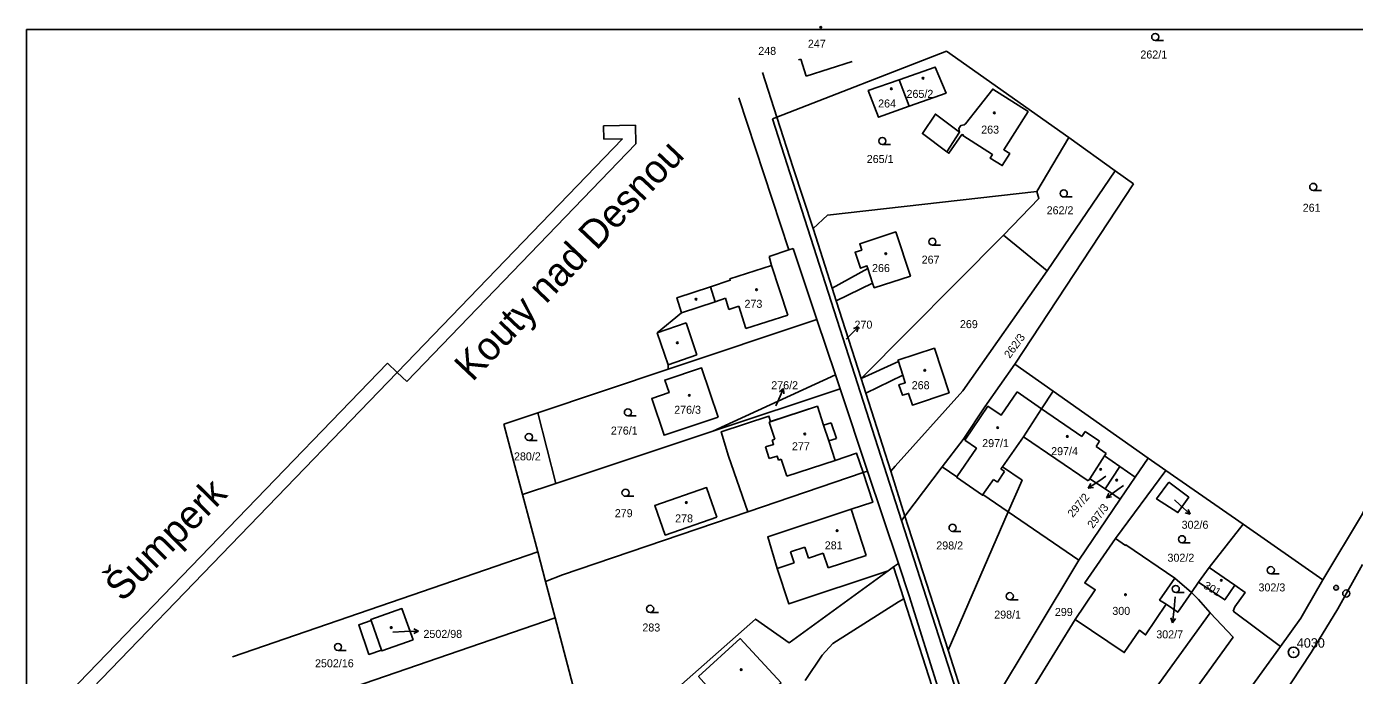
# Model space of a CAD drawing. Extents: x -558358 to -557517, y -1073785 to -1073189.
# Drawn here: x -558357.5 to -558075.5, y -1073327.3 to -1073189.5 of the extents above; entities that cross this region are included whole.
import ezdxf

# ---------------------------------------------------------------- set-up
doc = ezdxf.new("R2010")
doc.units = 0
for name, color, linetype in [('Hranice parcel', 7, 'Continuous'), ('Kolej', 7, 'Continuous'), ('Návěst místo trati', 7, 'Continuous'), ('Parcelní čísla', 7, 'Continuous'), ('Pop  PČ popisy', 7, 'Continuous'), ('Svazek obcí údolí Desné', 7, 'Continuous'), ('Vnitřní kresba', 7, 'Continuous'), ('Vrstva 1', 7, 'Continuous'), ('Vrstva 60', 7, 'Continuous'), ('Značky budov', 7, 'Continuous'), ('Značky kultur', 7, 'Continuous')]:
    doc.layers.add(name, color=color, linetype=linetype)

msp = doc.modelspace()

# ---------------------------------------------------------------- linework, layer by layer
at = {"layer": 'Hranice parcel'}
for p, q in [((-558198.15, -1073208.7), (-558162.11, -1073194.7)), ((-558162.11, -1073194.7), (-558136.18, -1073212.99)), ((-558198.15, -1073208.7), (-558201.24, -1073199.21)), ((-558170.04, -1073206.37), (-558172.21, -1073200.74)), ((-558195.64, -1073236.88), (-558206.21, -1073204.6)), ((-558199.08, -1073209.06), (-558198.15, -1073208.7)), ((-558171.71, -1073294.39), (-558199.08, -1073209.06)), ((-558136.18, -1073212.99), (-558142.95, -1073224.45)), ((-558136.18, -1073212.99), (-558126.3, -1073220.06)), ((-558140.75, -1073241.36), (-558126.3, -1073220.06)), ((-558126.3, -1073220.06), (-558122.4, -1073222.85)), ((-558122.4, -1073222.85), (-558147.61, -1073261.18)), ((-558190.48, -1073232.36), (-558186.42, -1073245.02)), ((-558180.27, -1073264.19), (-558150.02, -1073233.76)), ((-558150.02, -1073233.76), (-558140.75, -1073241.36)), ((-558199.8, -1073238.31), (-558195.64, -1073236.88)), ((-558194.69, -1073236.56), (-558195.64, -1073236.88)), ((-558194.69, -1073236.56), (-558189.64, -1073251.69)), ((-558186.42, -1073245.02), (-558185.55, -1073247.73)), ((-558185.55, -1073247.73), (-558180.27, -1073264.19)), ((-558221.22, -1073262.24), (-558189.64, -1073251.69)), ((-558189.64, -1073251.69), (-558185.73, -1073263.4)), ((-558248.97, -1073271.5), (-558221.22, -1073262.24)), ((-558211.74, -1073275.38), (-558185.73, -1073263.4)), ((-558185.73, -1073263.4), (-558184.74, -1073266.37)), ((-558147.61, -1073261.18), (-558139.47, -1073266.91)), ((-558180.27, -1073264.19), (-558179.28, -1073267.3)), ((-558184.74, -1073266.37), (-558211.74, -1073275.38)), ((-558184.74, -1073266.37), (-558178.92, -1073283.85)), ((-558179.28, -1073267.3), (-558173.98, -1073283.88)), ((-558139.47, -1073266.91), (-558119.31, -1073281.1)), ((-558256.16, -1073273.9), (-558248.97, -1073271.5)), ((-558248.97, -1073271.5), (-558245.1, -1073286.51)), ((-558254.1, -1073281.66), (-558256.16, -1073273.9)), ((-558185.53, -1073276.94), (-558186.65, -1073273.58)), ((-558211.74, -1073275.38), (-558245.1, -1073286.51)), ((-558252.2, -1073288.86), (-558254.1, -1073281.66)), ((-558170.97, -1073293.42), (-558163.02, -1073282.94)), ((-558128.43, -1073287.66), (-558125.31, -1073282.88)), ((-558122.04, -1073285.13), (-558125.31, -1073282.88)), ((-558122.04, -1073285.13), (-558119.31, -1073281.1)), ((-558119.31, -1073281.1), (-558115.55, -1073283.75)), ((-558204.33, -1073292.51), (-558179.86, -1073284.17)), ((-558179.86, -1073284.17), (-558178.92, -1073283.85)), ((-558178.92, -1073283.85), (-558172.36, -1073303.47)), ((-558173.98, -1073283.88), (-558170.97, -1073293.42)), ((-558126.22, -1073298.15), (-558115.55, -1073283.75)), ((-558125.21, -1073289.82), (-558122.04, -1073285.13)), ((-558115.55, -1073283.75), (-558099.14, -1073295.15)), ((-558245.1, -1073286.51), (-558252.2, -1073288.86)), ((-558128.43, -1073287.66), (-558125.21, -1073289.82)), ((-558252.2, -1073288.86), (-558248.97, -1073301.04)), ((-558134.04, -1073302.76), (-558125.21, -1073289.82)), ((-558171.71, -1073294.39), (-558170.97, -1073293.42)), ((-558161.8, -1073321.91), (-558170.97, -1073293.42)), ((-558149, -1073292.52), (-558161.8, -1073321.91)), ((-558149, -1073292.52), (-558134.04, -1073302.76)), ((-558106.35, -1073304.33), (-558099.14, -1073295.15)), ((-558099.14, -1073295.15), (-558082.18, -1073306.93)), ((-558313.8, -1073323.28), (-558248.97, -1073301.04)), ((-558248.97, -1073301.04), (-558247.31, -1073307.29)), ((-558156.12, -1073339.58), (-558134.04, -1073302.76)), ((-558174.53, -1073305.05), (-558173.36, -1073304.2)), ((-558173.36, -1073304.2), (-558172.36, -1073303.47)), ((-558171.18, -1073310.99), (-558173.36, -1073304.2)), ((-558106.35, -1073304.33), (-558108.61, -1073307.47)), ((-558100.91, -1073308.09), (-558106.35, -1073304.33)), ((-558247.31, -1073307.29), (-558245.27, -1073315.03)), ((-558113.61, -1073306.59), (-558110.09, -1073309.68)), ((-558110.09, -1073309.68), (-558108.61, -1073307.47)), ((-558171.18, -1073310.99), (-558158.75, -1073349.79)), ((-558146.53, -1073369.85), (-558106.1, -1073313.94)), ((-558101.25, -1073313.61), (-558091.21, -1073321.1)), ((-558245.27, -1073315.03), (-558311.02, -1073337.58)), ((-558245.27, -1073315.03), (-558240.15, -1073334.41)), ((-558153.86, -1073346.35), (-558134.81, -1073315.38)), ((-558156.12, -1073339.58), (-558161.8, -1073321.91))]:
    msp.add_line(p, q, dxfattribs=at)
for points in [[(-558172.21, -1073200.74), (-558164.51, -1073198.05), (-558162.21, -1073203.59), (-558170.04, -1073206.37)], [(-558172.21, -1073200.74), (-558178.74, -1073203.06), (-558176.58, -1073208.71), (-558170.04, -1073206.37)], [(-558159.35, -1073211.86), (-558164.49, -1073208.05), (-558167.25, -1073212.17), (-558162.05, -1073216.04), (-558161.61, -1073216.37), (-558158.87, -1073212.35), (-558158.54, -1073212.45), (-558158.65, -1073212.62), (-558152.39, -1073216.66), (-558152.86, -1073217.38), (-558150.28, -1073218.99), (-558148.7, -1073216.44), (-558149.97, -1073215.63), (-558144.81, -1073207.5), (-558152.32, -1073202.74), (-558158.11, -1073210.08), (-558158.35, -1073210.31), (-558159.12, -1073210.49), (-558159.48, -1073211.13), (-558159.35, -1073211.86)], [(-558198.15, -1073208.7), (-558194.7, -1073219.45), (-558190.48, -1073232.36)], [(-558190.48, -1073232.36), (-558187.44, -1073229.54), (-558142.95, -1073224.45)], [(-558142.95, -1073224.45), (-558142.49, -1073225.95), (-558150.02, -1073233.76)], [(-558185.55, -1073247.73), (-558177.82, -1073243.95), (-558177.49, -1073244.94), (-558169.79, -1073242.44), (-558172.9, -1073233.07), (-558180.56, -1073235.6), (-558180.13, -1073236.92), (-558181.54, -1073237.39), (-558180.43, -1073240.78), (-558179.03, -1073240.27), (-558178.83, -1073240.86), (-558186.42, -1073245.02)], [(-558199.8, -1073238.31), (-558199.29, -1073240.2), (-558208.14, -1073243.05), (-558208.05, -1073243.33), (-558212.29, -1073244.72), (-558219.4, -1073247.05), (-558218.39, -1073250.28), (-558223.57, -1073254.53), (-558221.27, -1073261.29), (-558221.22, -1073262.24)], [(-558140.75, -1073241.36), (-558158.68, -1073266.81), (-558173.01, -1073282.83), (-558173.98, -1073283.88)], [(-558179.28, -1073267.3), (-558171.41, -1073263.5), (-558170.89, -1073265.11), (-558172.23, -1073265.52), (-558171.5, -1073267.74), (-558170.17, -1073267.35), (-558169.36, -1073269.84), (-558161.57, -1073267.22), (-558164.69, -1073257.79), (-558172.45, -1073260.31), (-558172.35, -1073260.6), (-558180.27, -1073264.19)], [(-558210.64, -1073272.4), (-558222.13, -1073276.25), (-558224.75, -1073268.45), (-558221.07, -1073267.2), (-558221.97, -1073264.55), (-558214.15, -1073261.94), (-558210.64, -1073272.4)], [(-558163.02, -1073282.94), (-558158.61, -1073277.12), (-558153.96, -1073270.21), (-558147.61, -1073261.18)], [(-558149, -1073292.52), (-558146.08, -1073285.8), (-558150.24, -1073282.94), (-558145.79, -1073276.6), (-558141.97, -1073270.62), (-558139.47, -1073266.91)], [(-558186.65, -1073273.58), (-558188.24, -1073274.09), (-558189.55, -1073270.09), (-558199.49, -1073273.33), (-558199.86, -1073272.19), (-558209.99, -1073275.5), (-558208.43, -1073280.69), (-558204.33, -1073292.51)], [(-558179.86, -1073284.17), (-558181.24, -1073280.09), (-558185.8, -1073281.59), (-558187.15, -1073277.46), (-558185.53, -1073276.94)], [(-558163.02, -1073282.94), (-558159.92, -1073285.05), (-558159.98, -1073285.15), (-558154.48, -1073289), (-558154.38, -1073288.84), (-558149, -1073292.52)], [(-558125.31, -1073282.88), (-558128.57, -1073280.64), (-558131.66, -1073285.5), (-558128.43, -1073287.66)], [(-558179.86, -1073284.17), (-558177.8, -1073290.48), (-558182.36, -1073291.97), (-558200.11, -1073297.8), (-558198.12, -1073304.57), (-558195.6, -1073312.09), (-558174.53, -1073305.05)], [(-558210.92, -1073293.66), (-558221.88, -1073297.46), (-558224.1, -1073291.16), (-558213.08, -1073287.38), (-558210.92, -1073293.66)], [(-558114.88, -1073286.21), (-558110.67, -1073289.41), (-558112.99, -1073292.67), (-558117.52, -1073289.79), (-558114.88, -1073286.21)], [(-558247.31, -1073307.29), (-558243.66, -1073305.93), (-558204.33, -1073292.51)], [(-558140.29, -1073392.34), (-558154.66, -1073347.35), (-558171.71, -1073294.39)], [(-558134.81, -1073315.38), (-558130.55, -1073309.06), (-558132.76, -1073307.6), (-558126.22, -1073298.15)], [(-558113.61, -1073306.59), (-558124.02, -1073299.5), (-558124.12, -1073299.64), (-558126.22, -1073298.15)], [(-558237.16, -1073345.74), (-558202.67, -1073315.29), (-558195.58, -1073320.33), (-558174.53, -1073305.05)], [(-558172.36, -1073303.47), (-558170.06, -1073310.34), (-558157.85, -1073349.12), (-558143.83, -1073396.83)], [(-558115.48, -1073312.12), (-558116.87, -1073311.27), (-558113.61, -1073306.59)], [(-558108.61, -1073307.47), (-558103.03, -1073311.24), (-558100.91, -1073308.09)], [(-558100.91, -1073308.09), (-558098.7, -1073309.62), (-558100.86, -1073312.72), (-558101.25, -1073313.61)], [(-558192.17, -1073328.33), (-558188.55, -1073322.99), (-558186.3, -1073320.49), (-558172.32, -1073311.63), (-558171.18, -1073310.99)], [(-558110.09, -1073309.68), (-558113.01, -1073313.83), (-558115.48, -1073312.12)], [(-558106.1, -1073313.94), (-558108.58, -1073311.13), (-558110.09, -1073309.68)], [(-558275.45, -1073319.73), (-558282.1, -1073322.07), (-558282.17, -1073321.87), (-558284.8, -1073322.78), (-558286.97, -1073316.53), (-558284.37, -1073315.62), (-558284.44, -1073315.41), (-558277.79, -1073313.08), (-558275.45, -1073319.73)], [(-558106.1, -1073313.94), (-558101.27, -1073319.14), (-558143.89, -1073378.07)], [(-558134.81, -1073315.38), (-558124.37, -1073322.4), (-558121.16, -1073317.67), (-558119.85, -1073318.64), (-558115.48, -1073312.12)], [(-558197.27, -1073328.8), (-558205.94, -1073319.43), (-558214.79, -1073327.48), (-558206.42, -1073336.91), (-558197.27, -1073328.8)]]:
    msp.add_lwpolyline(points, dxfattribs=at)
at = {"layer": 'Kolej'}
msp.add_lwpolyline([(-558166.64, -1073442.09), (-558164.78, -1073439.38), (-558155.66, -1073426.13), (-558147.22, -1073413.85), (-558143.69, -1073408.73), (-558141.06, -1073404.9), (-558137.3, -1073399.44), (-558134.57, -1073395.46), (-558131.72, -1073391.31), (-558124.89, -1073381.38), (-558115.4, -1073367.56), (-558106.18, -1073354.16), (-558097.49, -1073341.51), (-558095.26, -1073338.27), (-558090.95, -1073331.93), (-558084.7, -1073322.4), (-558079.04, -1073313.09), (-558073.77, -1073303.7)], dxfattribs=at)
at = {"layer": 'Návěst místo trati'}
msp.add_line((-558079.43, -1073308.65), (-558079.33, -1073308.65), dxfattribs=at)
for centre, radius in [((-558079.38, -1073308.65), 0.5), ((-558077.22, -1073309.86), 0.75)]:
    msp.add_circle(centre, radius, dxfattribs=at)
at = {"layer": 'Pop  PČ popisy'}
for p, q in [((-558182.95, -1073255.34), (-558180.79, -1073253.26)), ((-558180.79, -1073253.26), (-558181.86, -1073253.59)), ((-558180.79, -1073253.26), (-558181.16, -1073254.31)), ((-558183.46, -1073255.83), (-558182.95, -1073255.34)), ((-558197.94, -1073269.07), (-558196.72, -1073266.33)), ((-558196.72, -1073266.33), (-558197.58, -1073267.04)), ((-558196.72, -1073266.33), (-558196.67, -1073267.45)), ((-558198.36, -1073270.02), (-558197.94, -1073269.07)), ((-558129.56, -1073285.83), (-558132.05, -1073287.51)), ((-558128.29, -1073284.96), (-558129.56, -1073285.83)), ((-558132.05, -1073287.51), (-558131.5, -1073286.53)), ((-558132.05, -1073287.51), (-558130.94, -1073287.36)), ((-558125.73, -1073287.76), (-558128.16, -1073289.52)), ((-558128.16, -1073289.52), (-558127.64, -1073288.53)), ((-558124.56, -1073286.91), (-558125.73, -1073287.76)), ((-558128.16, -1073289.52), (-558127.05, -1073289.34)), ((-558113.72, -1073290), (-558112.59, -1073291.03)), ((-558112.59, -1073291.03), (-558110.36, -1073293.04)), ((-558110.36, -1073293.04), (-558111.44, -1073292.74)), ((-558110.36, -1073293.04), (-558110.77, -1073292)), ((-558113.53, -1073310.57), (-558113.79, -1073313.11)), ((-558113.79, -1073313.11), (-558114.1, -1073316.09)), ((-558114.1, -1073316.09), (-558114.5, -1073315.05)), ((-558114.1, -1073316.09), (-558113.5, -1073315.15)), ((-558279.76, -1073318.04), (-558277.28, -1073317.94)), ((-558277.28, -1073317.94), (-558274.28, -1073317.83)), ((-558274.28, -1073317.83), (-558275.3, -1073317.37)), ((-558274.28, -1073317.83), (-558275.26, -1073318.37))]:
    msp.add_line(p, q, dxfattribs=at)
at = {"layer": 'Svazek obcí údolí Desné'}
for points in [[(-558082.18, -1073306.93), (-558073.77, -1073292.96), (-558066.53, -1073276.76), (-558060.05, -1073257.85), (-558056.4, -1073244.89), (-558045.6, -1073201.5), (-558043.17, -1073190.09)], [(-558082.18, -1073306.93), (-558086.02, -1073313.63), (-558086.89, -1073315.11), (-558091.21, -1073321.1)], [(-558091.21, -1073321.1), (-558099.53, -1073332.65), (-558131.71, -1073378.11), (-558132.32, -1073380.12), (-558138.4, -1073389.94), (-558139.67, -1073391.56)]]:
    msp.add_lwpolyline(points, dxfattribs=at)
at = {"layer": 'Vnitřní kresba'}
for p, q in [((-558193.6, -1073196.55), (-558193.1, -1073196.39)), ((-558193.1, -1073196.39), (-558191.93, -1073199.98)), ((-558191.93, -1073199.98), (-558182.14, -1073196.86)), ((-558162.05, -1073216.04), (-558159.35, -1073211.86)), ((-558199.29, -1073240.2), (-558195.85, -1073250.73)), ((-558178.83, -1073240.86), (-558177.82, -1073243.95)), ((-558212.29, -1073244.72), (-558211.3, -1073247.89)), ((-558218.39, -1073250.28), (-558211.3, -1073247.89)), ((-558211.3, -1073247.89), (-558209.09, -1073247.14)), ((-558209.09, -1073247.14), (-558208.34, -1073249.51)), ((-558208.34, -1073249.51), (-558206.26, -1073248.85)), ((-558206.26, -1073248.85), (-558204.74, -1073253.59)), ((-558204.74, -1073253.59), (-558195.85, -1073250.73)), ((-558223.57, -1073254.53), (-558217.44, -1073252.39)), ((-558217.44, -1073252.39), (-558215.14, -1073259.16)), ((-558221.27, -1073261.29), (-558215.14, -1073259.16)), ((-558172.35, -1073260.6), (-558171.41, -1073263.5)), ((-558147.14, -1073267.06), (-558141.97, -1073270.62)), ((-558189.55, -1073270.09), (-558199.78, -1073273.49)), ((-558141.97, -1073270.62), (-558133.4, -1073276.52)), ((-558199.78, -1073273.49), (-558198.6, -1073277.11)), ((-558188.24, -1073274.09), (-558187.15, -1073277.46)), ((-558198.6, -1073277.11), (-558199.14, -1073277.31)), ((-558145.79, -1073276.6), (-558132.02, -1073285.94)), ((-558133.4, -1073276.52), (-558132.65, -1073275.44)), ((-558132.65, -1073275.44), (-558129.62, -1073277.52)), ((-558130.36, -1073278.61), (-558129.62, -1073277.52)), ((-558200.56, -1073278.74), (-558199.78, -1073281.19)), ((-558130.36, -1073278.61), (-558128.2, -1073280.1)), ((-558128.57, -1073280.64), (-558128.2, -1073280.1)), ((-558197.83, -1073281.52), (-558197.23, -1073281.35)), ((-558197.23, -1073281.35), (-558196.05, -1073284.95)), ((-558196.05, -1073284.95), (-558185.8, -1073281.59)), ((-558150.56, -1073283.39), (-558150.24, -1073282.94)), ((-558154.38, -1073288.84), (-558152.12, -1073285.63)), ((-558152.12, -1073285.63), (-558151.33, -1073286.18)), ((-558151.33, -1073286.18), (-558149.78, -1073283.94)), ((-558150.56, -1073283.39), (-558149.78, -1073283.94)), ((-558132.02, -1073285.94), (-558131.66, -1073285.5)), ((-558182.36, -1073291.97), (-558179.17, -1073301.77)), ((-558195.29, -1073301.04), (-558192.22, -1073300.02)), ((-558192.22, -1073300.02), (-558191.45, -1073302.33)), ((-558195.29, -1073301.04), (-558194.51, -1073303.36)), ((-558191.45, -1073302.33), (-558188.34, -1073301.29)), ((-558188.34, -1073301.29), (-558187.3, -1073304.42)), ((-558187.3, -1073304.42), (-558179.17, -1073301.77)), ((-558198.12, -1073304.57), (-558194.51, -1073303.36)), ((-558284.37, -1073315.62), (-558282.17, -1073321.87))]:
    msp.add_line(p, q, dxfattribs=at)
for points in [[(-558147.14, -1073267.06), (-558150.53, -1073272.01), (-558153.32, -1073270.09), (-558158.27, -1073277.3)], [(-558200.56, -1073278.74), (-558198.86, -1073278.21), (-558199.14, -1073277.31)], [(-558159.92, -1073285.05), (-558155.77, -1073279.02), (-558158.27, -1073277.3)], [(-558197.83, -1073281.52), (-558198.09, -1073280.68), (-558199.78, -1073281.19)]]:
    msp.add_lwpolyline(points, dxfattribs=at)
at = {"layer": 'Vrstva 1'}
for p, q in [((-558357.53, -1073784.09), (-558357.53, -1073190.09)), ((-558357.53, -1073190.09), (-557516.53, -1073190.09)), ((-558228.16, -1073210.39), (-558235.01, -1073210.51)), ((-558235.01, -1073210.51), (-558234.9, -1073213.34)), ((-558228.09, -1073214.39), (-558228.16, -1073210.39)), ((-558230.95, -1073213.27), (-558278.82, -1073262.89)), ((-558276.78, -1073264.86), (-558228.09, -1073214.39)), ((-558234.9, -1073213.34), (-558230.95, -1073213.27)), ((-558280.86, -1073260.92), (-558348.4, -1073330.92)), ((-558345.54, -1073332.05), (-558278.82, -1073262.89)), ((-558278.82, -1073262.89), (-558280.86, -1073260.92)), ((-558278.82, -1073262.89), (-558276.78, -1073264.86))]:
    msp.add_line(p, q, dxfattribs=at)
at = {"layer": 'Vrstva 60'}
msp.add_line((-558088.41, -1073322.35), (-558088.41, -1073322.35), dxfattribs=at)
msp.add_line((-558088.41, -1073322.35), (-558088.41, -1073322.35), dxfattribs=at)
for radius in [1.12, 0.045]:
    msp.add_circle((-558088.41, -1073322.35), radius, dxfattribs=at)
at = {"layer": 'Značky budov'}
for centre in [(-558188.83, -1073189.63), (-558167.13, -1073200.43), (-558173.84, -1073202.67), (-558151.98, -1073207.78), (-558175.02, -1073237.7), (-558202.48, -1073245.34), (-558215.35, -1073247.36), (-558219.32, -1073256.62), (-558166.74, -1073262.46), (-558216.76, -1073267.78), (-558151.26, -1073274.64), (-558192.23, -1073275.99), (-558136.46, -1073276.5), (-558129.37, -1073283.49), (-558125.99, -1073285.78), (-558217.39, -1073290.55), (-558185.37, -1073296.51), (-558103.76, -1073307.08), (-558124.11, -1073310.11), (-558280.08, -1073317.09), (-558205.73, -1073326.02)]:
    msp.add_circle(centre, 0.175, dxfattribs=at)
at = {"layer": 'Značky kultur'}
for p, q in [((-558117.8, -1073192.42), (-558116.05, -1073192.42)), ((-558175.76, -1073214.51), (-558174.01, -1073214.51)), ((-558137.22, -1073225.64), (-558135.47, -1073225.64)), ((-558084.24, -1073224.25), (-558082.49, -1073224.25)), ((-558165.13, -1073235.9), (-558163.38, -1073235.9)), ((-558229.81, -1073272.15), (-558228.06, -1073272.15)), ((-558250.84, -1073277.37), (-558249.09, -1073277.37)), ((-558230.31, -1073289.22), (-558228.56, -1073289.22)), ((-558160.84, -1073296.66), (-558159.09, -1073296.66)), ((-558112.12, -1073299.08), (-558110.37, -1073299.08)), ((-558093.24, -1073305.66), (-558091.49, -1073305.66)), ((-558148.68, -1073311.18), (-558146.93, -1073311.18)), ((-558113.43, -1073309.64), (-558111.68, -1073309.64)), ((-558225.08, -1073313.87), (-558223.33, -1073313.87)), ((-558291.38, -1073321.96), (-558289.63, -1073321.96))]:
    msp.add_line(p, q, dxfattribs=at)
for centre in [(-558117.8, -1073191.67), (-558175.76, -1073213.76), (-558084.24, -1073223.5), (-558137.22, -1073224.89), (-558165.13, -1073235.15), (-558229.81, -1073271.4), (-558250.84, -1073276.62), (-558230.31, -1073288.47), (-558160.84, -1073295.91), (-558112.12, -1073298.33), (-558093.24, -1073304.91), (-558113.43, -1073308.89), (-558148.68, -1073310.43), (-558225.08, -1073313.12), (-558291.38, -1073321.21)]:
    msp.add_circle(centre, 0.75, dxfattribs=at)

# ---------------------------------------------------------------- texts
at = {"layer": 'Parcelní čísla'}
for s, p in [('247', (-558191.57, -1073193.95)), ('248', (-558202.11, -1073195.47)), ('262/1', (-558120.95, -1073196.24)), ('265/2', (-558170.62, -1073204.6)), ('264', (-558176.65, -1073206.64)), ('263', (-558154.76, -1073212.19)), ('265/1', (-558179.07, -1073218.43)), ('262/2', (-558140.86, -1073229.32)), ('261', (-558086.47, -1073228.79)), ('266', (-558177.95, -1073241.59)), ('267', (-558167.41, -1073239.81)), ('273', (-558205.04, -1073249.19)), ('270', (-558181.67, -1073253.61)), ('269', (-558159.28, -1073253.5)), ('276/2', (-558199.35, -1073266.48)), ('268', (-558169.52, -1073266.47)), ('276/3', (-558219.97, -1073271.69)), ('276/1', (-558233.42, -1073276.11)), ('297/1', (-558154.55, -1073278.77)), ('280/2', (-558254, -1073281.59)), ('277', (-558194.96, -1073279.44)), ('297/4', (-558139.9, -1073280.48)), ('279', (-558232.59, -1073293.65)), ('278', (-558219.77, -1073294.76)), ('302/6', (-558112.19, -1073296.11)), ('281', (-558187.99, -1073300.48)), ('298/2', (-558164.3, -1073300.51)), ('302/2', (-558115.19, -1073303.11)), ('302/3', (-558095.86, -1073309.42)), ('298/1', (-558151.99, -1073315.19)), ('299', (-558139.11, -1073314.63)), ('300', (-558126.91, -1073314.4)), ('283', (-558226.73, -1073317.93)), ('2502/98', (-558273.23, -1073319.29)), ('302/7', (-558117.57, -1073319.39)), ('2502/16', (-558296.26, -1073325.53))]:
    msp.add_text(s, height=1.7, dxfattribs=at).set_placement(p)
for s, rotation, p in [('262/3', 54, (-558148.67, -1073260.04)), ('297/2', 50, (-558135.3, -1073293.83)), ('297/3', 53, (-558131.02, -1073296.16)), ('301', 330, (-558107.72, -1073308.64))]:
    msp.add_text(s, height=1.7, rotation=rotation, dxfattribs=at).set_placement(p)
at = {"layer": 'Vrstva 1'}
for s, rotation, p in [('Kouty nad Desnou', 46.6457, (-558262.82, -1073265.06)), ('Šumperk', 45.2335, (-558337.2, -1073311.84))]:
    msp.add_text(s, height=6, rotation=rotation, dxfattribs=at).set_placement(p)
at = {"layer": 'Vrstva 60'}
msp.add_text('4030', height=2, dxfattribs=at).set_placement((-558087.72, -1073321.36))

doc.saveas('drawing.dxf')
